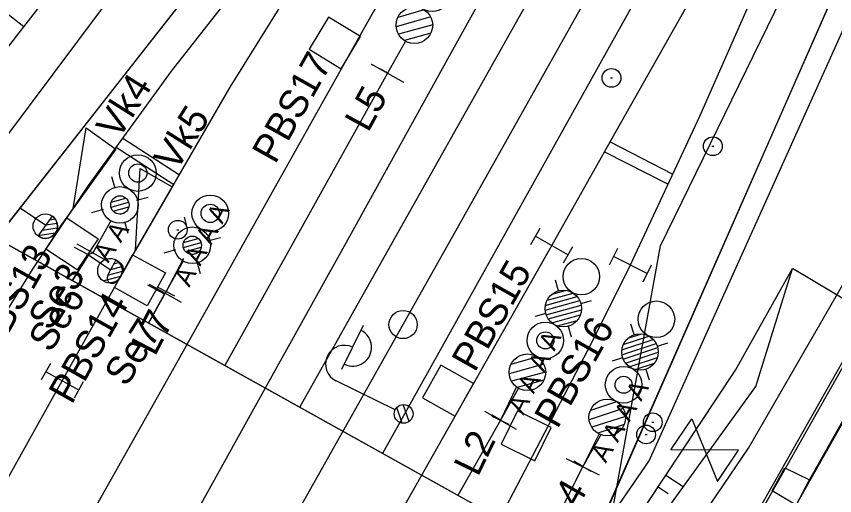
# Model space of a CAD drawing. Extents: x -781083 to -763634, y -1029516 to -1022695.
# Drawn here: x -765004.08 to -764960.51, y -1023880.88 to -1023855.35 of the extents above; entities that cross this region are included whole.
import ezdxf

# ---------------------------------------------------------------- set-up
doc = ezdxf.new("R2010")
doc.units = 0
for name, color, linetype in [('Default', 7, 'Continuous'), ('Hranice parcel', 7, 'Continuous'), ('PS120111-MOK', 7, 'Continuous'), ('PS_12-01-10_Kabelizace_nove_kabelizace', 7, 'Continuous'), ('PS_12-01-11_SZZ_Slany_nove_prvky', 7, 'Continuous'), ('PS_12-01-11_SZZ_Slany_nove_prvky_popis', 7, 'Continuous'), ('PS_12-01-11_SZZ_Slany_rusene_prvky', 7, 'Continuous'), ('PS_12-01-11_SZZ_Slany_rusene_prvky_popis', 7, 'Continuous'), ('SO128401_EOV_trasa', 7, 'Continuous'), ('Vnitřní kresba', 7, 'Continuous'), ('Vrstva 1', 7, 'Continuous'), ('Vrstva 17', 7, 'Continuous'), ('Vrstva 21', 7, 'Continuous'), ('Vrstva 23', 7, 'Continuous'), ('Vrstva 25', 7, 'Continuous'), ('Vrstva 3', 7, 'Continuous'), ('Vrstva 48', 7, 'Continuous'), ('Vrstva 49', 7, 'Continuous'), ('Vrstva 50', 7, 'Continuous'), ('Vrstva 7', 7, 'Continuous'), ('ČD Telematika_TK', 7, 'Continuous')]:
    doc.layers.add(name, color=color, linetype=linetype)

# ---------------------------------------------------------------- blocks, each defined once
blk = doc.blocks.new('C669')
at = {"layer": 'Vrstva 25'}
for p, q in [((0, 5), (0, 40)), ((7, 40), (33, 40)), ((-4.78, -1.46), (1.44, 4.76)), ((-2.39, -4.37), (4.38, 2.4))]:
    blk.add_line(p, q, dxfattribs=at)
blk.add_circle((0, 0), 5, dxfattribs=at)
for centre, start, end in [((10, 40), 0, 180), ((20, 39.88), 179.2974, 0.7026)]:
    blk.add_arc(centre, 10, start, end, dxfattribs=at)
blk = doc.blocks.new('C687')
at = {"layer": 'Vrstva 21'}
blk.add_lwpolyline([(-10, -15), (10, -15), (-10, 15), (10, 15), (-10, -15)], dxfattribs=at)
blk = doc.blocks.new('C053_4')
at = {"layer": 'Vrstva 50'}
blk.add_line((-0.5, 0), (0.5, 0), dxfattribs=at)
blk.add_circle((0, 0), 5, dxfattribs=at)
blk = doc.blocks.new('C649_1')
at = {"layer": 'Vrstva 3'}
for p, q in [((-5, 10), (5, 10)), ((0, 10), (0, -10)), ((-5, -10), (5, -10))]:
    blk.add_line(p, q, dxfattribs=at)
blk = doc.blocks.new('POINT_DISPLAY')
at = {"layer": 'Default'}
blk.add_line((0, 0), (0, 0), dxfattribs=at)
blk = doc.blocks.new('C335')
at = {"layer": 'Vrstva 7'}
blk.add_blockref('POINT_DISPLAY', (0, 0), dxfattribs=at)
blk = doc.blocks.new('C513_17')
at = {"layer": 'Vrstva 7'}
blk.add_circle((0, 0), 7.5, dxfattribs=at)
blk = doc.blocks.new('C016')
at = {"layer": 'PS_12-01-11_SZZ_Slany_rusene_prvky'}
for p, q in [((0.01, 5), (-0.01, -5)), ((19.8, 0), (0, 0))]:
    blk.add_line(p, q, dxfattribs=at)
blk = doc.blocks.new('C016_1')
at = {"layer": 'PS_12-01-11_SZZ_Slany_rusene_prvky'}
for p, q in [((0, 4.99), (0, -4.99)), ((19.8, 0), (0, 0))]:
    blk.add_line(p, q, dxfattribs=at)
blk = doc.blocks.new('NS12')
at = {"layer": 'PS_12-01-11_SZZ_Slany_nove_prvky'}
for p, q in [((-10.61, 115.61), (-17, 122)), ((10.61, 115.61), (17, 122)), ((-14.95, 104.3), (0.71, 119.96)), ((-14.06, 99.88), (5.12, 119.06)), ((-13.82, 110.73), (-5.7, 118.86)), ((-12.24, 96.4), (8.61, 117.25)), ((-9.72, 93.62), (11.4, 114.74)), ((-6.52, 91.51), (13.48, 111.52)), ((-2.5, 90.23), (14.77, 107.5)), ((2.88, 90.31), (14.72, 102.15)), ((-10.61, 94.39), (-17, 88)), ((10.61, 94.39), (17, 88)), ((0.97, 59.97), (-14.97, 44.03)), ((8.42, 57.42), (-12.42, 36.58)), ((12.99, 52.49), (-7.8, 32.19)), ((14.97, 45.97), (-1, 30)), ((0, 30), (0, 0)), ((-15, 0), (15, 0))]:
    blk.add_line(p, q, dxfattribs=at)
for centre, radius in [((0, 135), 15), ((0, 105), 15), ((0, 75), 15), ((0, 75), 7), ((0, 45), 15)]:
    blk.add_circle(centre, radius, dxfattribs=at)
blk = doc.blocks.new('NS12_1')
at = {"layer": 'PS_12-01-11_SZZ_Slany_nove_prvky'}
for p, q in [((-10.61, 115.61), (-17, 122)), ((10.61, 115.61), (17, 122)), ((-14.95, 104.3), (0.71, 119.96)), ((-14.06, 99.88), (5.12, 119.06)), ((-13.82, 110.73), (-5.7, 118.86)), ((-12.24, 96.4), (8.61, 117.25)), ((-9.72, 93.62), (11.4, 114.74)), ((-6.52, 91.51), (13.48, 111.52)), ((-2.5, 90.23), (14.77, 107.5)), ((2.88, 90.31), (14.72, 102.15)), ((-10.61, 94.39), (-17, 88)), ((10.61, 94.39), (17, 88)), ((0.97, 59.97), (-14.97, 44.03)), ((8.42, 57.42), (-12.42, 36.58)), ((12.99, 52.49), (-7.8, 32.19)), ((14.97, 45.97), (-1, 30)), ((0, 30), (0, 0)), ((-15, 0), (15, 0))]:
    blk.add_line(p, q, dxfattribs=at)
for centre, radius in [((0, 135), 15), ((0, 105), 15), ((0, 75), 15), ((0, 75), 7), ((0, 45), 15)]:
    blk.add_circle(centre, radius, dxfattribs=at)
blk = doc.blocks.new('NS12_2')
at = {"layer": 'PS_12-01-11_SZZ_Slany_nove_prvky'}
for p, q in [((-10.61, 115.61), (-17, 122)), ((10.61, 115.61), (17, 122)), ((-14.95, 104.3), (0.71, 119.96)), ((-14.06, 99.88), (5.12, 119.06)), ((-13.82, 110.73), (-5.7, 118.86)), ((-12.24, 96.4), (8.61, 117.25)), ((-9.72, 93.62), (11.4, 114.74)), ((-6.52, 91.51), (13.48, 111.52)), ((-2.5, 90.23), (14.77, 107.5)), ((2.88, 90.31), (14.72, 102.15)), ((-10.61, 94.39), (-17, 88)), ((10.61, 94.39), (17, 88)), ((0.97, 59.97), (-14.97, 44.03)), ((8.42, 57.42), (-12.42, 36.58)), ((12.99, 52.49), (-7.8, 32.19)), ((14.97, 45.97), (-1, 30)), ((0, 30), (0, 0)), ((-15, 0), (15, 0))]:
    blk.add_line(p, q, dxfattribs=at)
for centre, radius in [((0, 135), 15), ((0, 105), 15), ((0, 75), 15), ((0, 75), 7), ((0, 45), 15)]:
    blk.add_circle(centre, radius, dxfattribs=at)
blk = doc.blocks.new('C016_2')
at = {"layer": 'PS_12-01-11_SZZ_Slany_rusene_prvky'}
for p, q in [((0, 5), (0, -5)), ((19.81, 0), (0, 0))]:
    blk.add_line(p, q, dxfattribs=at)
blk = doc.blocks.new('NS5')
at = {"layer": 'PS_12-01-11_SZZ_Slany_nove_prvky'}
for p, q in [((-10, 55), (-17, 62)), ((10, 55), (17, 62)), ((-7.3, 43.39), (1.61, 52.3)), ((-5.47, 39.92), (5.1, 50.48)), ((-2.23, 37.85), (7.13, 47.21)), ((3.76, 38.54), (6.45, 41.23)), ((-10, 35), (-17, 28)), ((10, 35), (17, 28)), ((0, 30), (0, 0)), ((-15, 0), (15, 0))]:
    blk.add_line(p, q, dxfattribs=at)
for centre, radius in [((0, 75), 15), ((0, 75), 7.5), ((0, 45), 15), ((0, 45), 7.5)]:
    blk.add_circle(centre, radius, dxfattribs=at)
blk = doc.blocks.new('C649_1_1')
at = {"layer": 'PS_12-01-11_SZZ_Slany_rusene_prvky'}
for p, q in [((-5, 10), (5, 10)), ((0, 10), (0, -10)), ((-5, -10), (5, -10))]:
    blk.add_line(p, q, dxfattribs=at)
blk = doc.blocks.new('SB11_3')
at = {"layer": 'PS_12-01-11_SZZ_Slany_nove_prvky'}
blk.add_lwpolyline([(-119.5, 188.9), (-222.8, 18), (-51.7, -85.4), (51.7, 85.4)], close=True, dxfattribs=at)
blk = doc.blocks.new('SB11_4')
at = {"layer": 'PS_12-01-11_SZZ_Slany_nove_prvky'}
blk.add_lwpolyline([(-124.8, 185.5), (-223.3, 11.4), (-49.2, -87), (49.2, 87)], close=True, dxfattribs=at)
blk = doc.blocks.new('SB11_5')
at = {"layer": 'PS_12-01-11_SZZ_Slany_nove_prvky'}
blk.add_lwpolyline([(-135.8, 177), (-222.6, 0.5), (-43.4, -88.3), (43.4, 88.3)], close=True, dxfattribs=at)
blk = doc.blocks.new('VU26_1')
at = {"layer": 'PS_12-01-11_SZZ_Slany_nove_prvky'}
for p, q in [((-95, 20), (-75, 20)), ((-84.76, 10.01), (-94.75, 20)), ((-80.54, 11.09), (-89.45, 20)), ((-77.53, 13.38), (-84.15, 20)), ((-75.56, 16.72), (-78.84, 20)), ((-60, 10), (-85, 10))]:
    blk.add_line(p, q, dxfattribs=at)
blk.add_lwpolyline([(0, 10), (-60, 10), (0, 40)], close=True, dxfattribs=at)
blk.add_lwpolyline([(-95, 20), (-75, 20)], dxfattribs=at)
blk.add_circle((-85, 20), 10, dxfattribs=at)
blk.add_arc((-85, 20), 10, 179.99624, 0.00163, dxfattribs=at)
blk.add_arc((-85, 20), 10, 179.99624, 0.00163, dxfattribs=at)
blk = doc.blocks.new('SB11_13')
at = {"layer": 'PS_12-01-11_SZZ_Slany_nove_prvky'}
blk.add_lwpolyline([(221.9, -27.9), (110.8, -194.2), (-55.5, -83.2), (55.5, 83.2)], close=True, dxfattribs=at)
blk = doc.blocks.new('SB11_14')
at = {"layer": 'PS_12-01-11_SZZ_Slany_nove_prvky'}
blk.add_lwpolyline([(223.4, -9.5), (126.4, -184.4), (-48.5, -87.5), (48.5, 87.5)], close=True, dxfattribs=at)

msp = doc.modelspace()

# ---------------------------------------------------------------- linework, layer by layer
at = {"layer": 'Hranice parcel'}
msp.add_lwpolyline([(-764938.97, -1023836.45), (-764967.04, -1023886), (-764962.72, -1023888.96), (-764967.7, -1023897.5)], dxfattribs=at)
at = {"layer": 'PS120111-MOK'}
msp.add_lwpolyline([(-765225.805, -1024328.474), (-765227.041, -1024327.403), (-765189.607, -1024263.284), (-765167.089, -1024223.521), (-765111.836, -1024124.939), (-765108.851, -1024119.501), (-765085.73, -1024077.899), (-765081.023, -1024080.523), (-765060.822, -1024044.042), (-765057.835, -1024038.647), (-765021.888, -1023965.037), (-765009.529, -1023945.01), (-764990.029, -1023909.994), (-764973.93, -1023884.565), (-764957.796, -1023847.878), (-764953.349, -1023837.037), (-764952.504, -1023834.976), (-764951.393, -1023835.06)], dxfattribs=at)
at = {"layer": 'PS_12-01-10_Kabelizace_nove_kabelizace'}
for p, q in [((-765005.156, -1023867.179), (-764967.937, -1023819.655)), ((-764988.994, -1023876.176), (-764968.535, -1023839.77)), ((-764963.233, -1023840.29), (-764984.582, -1023878.634)), ((-764957.796, -1023847.878), (-764973.93, -1023884.565)), ((-764985.188, -1023857.891), (-764984.306, -1023858.363)), ((-764984.313, -1023858.377), (-764992.987, -1023873.955)), ((-765003.883, -1023865.554), (-765002.509, -1023866.483)), ((-764996.151, -1023870.095), (-764997.052, -1023871.691)), ((-764978.311, -1023876.86), (-764980.57, -1023880.867)), ((-764978.311, -1023876.86), (-764978.778, -1023876.58)), ((-764973.926, -1023879.33), (-764974.394, -1023879.05)), ((-764973.929, -1023879.336), (-764975.974, -1023883.426))]:
    msp.add_line(p, q, dxfattribs=at)
for points in [[(-764973.93, -1023884.565), (-765004.981, -1023867.276), (-765005.156, -1023867.179)], [(-765001.107, -1023869.434), (-765000.245, -1023868.058), (-765000.982, -1023867.665)], [(-765001.107, -1023869.434), (-765000.245, -1023868.058), (-764999.075, -1023868.849)], [(-765000.005, -1023867.946), (-765000.245, -1023868.058), (-765001.106, -1023869.433)], [(-764997.052, -1023871.691), (-764996.187, -1023870.158), (-764997.084, -1023869.662)]]:
    msp.add_lwpolyline(points, dxfattribs=at)
at = {"layer": 'PS_12-01-11_SZZ_Slany_nove_prvky'}
for p, q in [((-764997.73, -1023867.811), (-764998.539, -1023869.221)), ((-764998.612, -1023868.471), (-764998.903, -1023868.55)), ((-764998.456, -1023868.934), (-764999.246, -1023869.148)), ((-764998.488, -1023868.69), (-764999.075, -1023868.849)), ((-764998.532, -1023869.207), (-764999.418, -1023869.447))]:
    msp.add_line(p, q, dxfattribs=at)
msp.add_lwpolyline([(-764995.791, -1023864.428), (-764997.73, -1023867.811), (-764997.482, -1023863.458)], close=True, dxfattribs=at)
msp.add_ellipse((-764999.102, -1023868.897), major_axis=(0.546, -0.353), ratio=0.999982, dxfattribs=at)
msp.add_open_spline([(-764999.103, -1023868.897), (-764998.779, -1023868.333), (-764998.779, -1023868.333), (-764998.779, -1023868.333), (-764998.215, -1023868.657), (-764998.539, -1023869.22), (-764998.862, -1023869.784), (-764999.426, -1023869.461), (-764999.103, -1023868.897)], degree=4, dxfattribs=at)
at = {"layer": 'SO128401_EOV_trasa'}
for points in [[(-764973.93, -1023884.565), (-765005.156, -1023867.179), (-764967.937, -1023819.655), (-764942.036, -1023784.592), (-764937.448, -1023776.793), (-764936.433, -1023777.403)], [(-765060.824, -1024044.045), (-765057.835, -1024038.647), (-765021.888, -1023965.037), (-765009.529, -1023945.01), (-764990.029, -1023909.994), (-764973.93, -1023884.565), (-764973.93, -1023884.565), (-764957.796, -1023847.878), (-764957.796, -1023847.878), (-764953.349, -1023837.037), (-764953.349, -1023837.037), (-764952.595, -1023837.444), (-764952.595, -1023837.444), (-764952.595, -1023837.444), (-764952.595, -1023837.444)]]:
    msp.add_lwpolyline(points, dxfattribs=at)
at = {"layer": 'Vnitřní kresba'}
msp.add_line((-764947.74, -1023855.04), (-764963.43, -1023882.91), dxfattribs=at)
at = {"layer": 'Vrstva 1'}
for points in [[(-765011.125, -1023882.032), (-765006.787, -1023874.584), (-765003.188, -1023868.775), (-765000.244, -1023864.367), (-764995.829, -1023858.264), (-764991.795, -1023853.119), (-764989.992, -1023850.92), (-764988.125, -1023848.704), (-764979.186, -1023837.995), (-764972.943, -1023830.075), (-764972.169, -1023829.066), (-764962.145, -1023815.837), (-764953.22, -1023803.742), (-764952.283, -1023802.457), (-764942.467, -1023789.001), (-764933.609, -1023776.857), (-764932.714, -1023775.624), (-764932.358, -1023775.126), (-764928.839, -1023770.209), (-764926.844, -1023767.42), (-764917.098, -1023753.973), (-764910.61, -1023742.572)], [(-765057.199, -1024002.967), (-765051.483, -1023992.806), (-765043.706, -1023978.953), (-765034.751, -1023962.958), (-765025.899, -1023947.163), (-765016.568, -1023930.575), (-765007.818, -1023915.05), (-764998.815, -1023899.045), (-764993.349, -1023889.308), (-764987.511, -1023878.918), (-764981.006, -1023867.343), (-764973.154, -1023853.353), (-764966.496, -1023841.495), (-764959.274, -1023828.66), (-764951.948, -1023815.612), (-764946.772, -1023806.407), (-764938.618, -1023791.934), (-764931.244, -1023778.835), (-764930.485, -1023777.473), (-764927.033, -1023771.438), (-764925.317, -1023768.417), (-764917.098, -1023753.973)], [(-765061.157, -1024000.548), (-765054.406, -1023988.525), (-765046.25, -1023974.042), (-765038.306, -1023959.907), (-765029.522, -1023944.29), (-765019.951, -1023927.223), (-765010.85, -1023911.039), (-765002.788, -1023896.651), (-764999.751, -1023891.219), (-764995.793, -1023884.104), (-764991.163, -1023875.777), (-764986.062, -1023866.575), (-764981.011, -1023857.454), (-764976.168, -1023848.713), (-764971.336, -1023840.024), (-764966.193, -1023830.79), (-764963.989, -1023826.843), (-764958.821, -1023817.674), (-764953.901, -1023808.973), (-764950.727, -1023803.418), (-764942.467, -1023789.001)], [(-765021.966, -1023959.899), (-765020.98, -1023958.139), (-765020.338, -1023956.998), (-765016.5, -1023950.137), (-765007.832, -1023934.643), (-765003.16, -1023926.347), (-764995.027, -1023911.884), (-764988.083, -1023899.535), (-764983.024, -1023890.503), (-764978.046, -1023881.533), (-764973.443, -1023872.721), (-764971.379, -1023868.593), (-764967.7, -1023860.663), (-764964.253, -1023852.828), (-764961.628, -1023846.609), (-764955.193, -1023831.268), (-764949.378, -1023817.406), (-764948.769, -1023815.942), (-764946.974, -1023811.649), (-764945.113, -1023807.171), (-764938.618, -1023791.934)], [(-765066.823, -1024000.8), (-765059.521, -1023987.798), (-765051.083, -1023972.749), (-765042.307, -1023957.114), (-765034.527, -1023943.229), (-765024.842, -1023926.012), (-765014.604, -1023907.749), (-765007.197, -1023894.564), (-765001.299, -1023884.061), (-764995.865, -1023874.378), (-764990.286, -1023864.419), (-764985.503, -1023855.894), (-764983.132, -1023851.684), (-764978.128, -1023842.798), (-764973.494, -1023834.781), (-764970.63, -1023830.052), (-764962.145, -1023815.837)], [(-764992.669, -1023917.221), (-764979.299, -1023898.88), (-764973.72, -1023891.071), (-764965.108, -1023878.355), (-764944.509, -1023842.632), (-764937.461, -1023829.77)], [(-765052.709, -1024004.781), (-765046.025, -1023992.89), (-765034.924, -1023973.118), (-765026.269, -1023957.734), (-765017.76, -1023942.588), (-765010.012, -1023928.764), (-765001.938, -1023914.334), (-764994.407, -1023900.905), (-764986.605, -1023887.067), (-764981.397, -1023877.846), (-764975.574, -1023867.554), (-764972.605, -1023862.288), (-764968.241, -1023854.565), (-764963.27, -1023845.769), (-764955.193, -1023831.268)], [(-765076.991, -1024009.249), (-765068.63, -1023994.356), (-765060.962, -1023980.666), (-765051.422, -1023963.636), (-765043.392, -1023949.298), (-765036.095, -1023936.274), (-765028.081, -1023921.999), (-765021.192, -1023909.705), (-765014.101, -1023897.058), (-765011.259, -1023891.988), (-765007.442, -1023885.157), (-765001.636, -1023874.768), (-764998.254, -1023868.714), (-764992.689, -1023859.115), (-764988.392, -1023852.179), (-764986.762, -1023849.668), (-764979.186, -1023837.995)]]:
    msp.add_lwpolyline(points, dxfattribs=at)
at = {"layer": 'Vrstva 17'}
for points in [[(-764984.37, -1023833.783), (-764994.207, -1023847.799), (-765035.2, -1023902.657), (-765053.308, -1023935.706), (-765077.185, -1023979.953), (-765108.689, -1023993.473), (-765147.863, -1024026.342)], [(-764965.992, -1023885.405), (-764965.453, -1023883.54), (-764958.526, -1023871.297), (-764951.567, -1023858.868)], [(-764958.526, -1023871.297), (-764962.765, -1023868.78)]]:
    msp.add_lwpolyline(points, dxfattribs=at)
at = {"layer": 'Vrstva 23'}
for points in [[(-764962.559, -1023881.396), (-764961.849, -1023880.039), (-764932.414, -1023827.868)], [(-764962.559, -1023881.396), (-764963.834, -1023880.627), (-764963.157, -1023879.401), (-764961.849, -1023880.039), (-764962.559, -1023881.396)]]:
    msp.add_lwpolyline(points, dxfattribs=at)
at = {"layer": 'Vrstva 48'}
for p, q in [((-765007.467, -1023852.954), (-765003.682, -1023855.896)), ((-764968.582, -1023880.415), (-764969.505, -1023879.805)), ((-764969.38, -1023880.786), (-764969.918, -1023880.43))]:
    msp.add_line(p, q, dxfattribs=at)
at = {"layer": 'Vrstva 49'}
for points in [[(-765026.593, -1023885.365), (-764999.705, -1023850.781), (-764986.63, -1023833.272), (-764978.594, -1023818.199), (-764974.02, -1023810.068), (-764969.31, -1023798.584)], [(-764984.64, -1023902.67), (-764964.718, -1023875.061), (-764962.765, -1023868.78)], [(-764984.64, -1023902.67), (-764965.796, -1023874.202), (-764962.765, -1023868.78)]]:
    msp.add_lwpolyline(points, dxfattribs=at)
at = {"layer": 'Vrstva 7'}
for p, q in [((-764998.41, -1023861.832), (-764995.398, -1023863.788)), ((-764972.466, -1023862.042), (-764969.134, -1023863.753)), ((-764998.762, -1023862.319), (-764995.699, -1023864.307)), ((-764972.762, -1023862.565), (-764969.386, -1023864.298))]:
    msp.add_line(p, q, dxfattribs=at)
at = {"layer": 'ČD Telematika_TK'}
for points in [[(-764972.556, -1023882.882), (-764969.78, -1023867.575), (-764954.962, -1023837.207), (-764946.646, -1023819.145), (-764922.208, -1023770.145), (-764907.866, -1023743.998)], [(-765046.807, -1024017.08), (-765029.13, -1023984.48), (-765018.689, -1023963.431), (-765009.158, -1023943.676), (-764986.584, -1023911.367), (-764975.521, -1023895.82), (-764979.204, -1023891.861), (-764970.396, -1023879.031), (-764960.103, -1023856.143), (-764944.124, -1023819.068), (-764943.31, -1023819.61)]]:
    msp.add_lwpolyline(points, dxfattribs=at)

# ---------------------------------------------------------------- block references
at = {"layer": 'PS_12-01-11_SZZ_Slany_nove_prvky'}
for name, p, xscale, yscale, rotation in [('NS12_2', (-764984.313, -1023858.377), 0.065, 0.065, -29.116206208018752), ('VU26_1', (-764998.25, -1023862.813), 0.06500000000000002, 0.065, 54.11746937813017), ('NS5', (-765000.005, -1023867.946), 0.065, 0.06499999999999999, -29.387467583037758), ('NS5', (-764996.152, -1023870.095), 0.065, 0.06499999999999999, -29.387467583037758), ('NS12_1', (-764978.311, -1023876.86), 0.06499999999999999, 0.06499999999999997, -29.414544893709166), ('NS12', (-764973.929, -1023879.336), 0.065, 0.065, -26.565051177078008)]:
    msp.add_blockref(name, p, dxfattribs=dict(at, xscale=xscale, yscale=yscale, rotation=rotation))
for name, p, xscale, yscale in [('SB11_3', (-764986.267, -1023857.286), 0.010000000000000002, 0.010000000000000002), ('SB11_13', (-765001.949, -1023866.92), 0.010000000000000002, 0.010000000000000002), ('SB11_14', (-764998.374, -1023868.922), 0.010000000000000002, 0.010000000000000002), ('SB11_4', (-764980.228, -1023875.779), 0.01, 0.01), ('SB11_5', (-764976.035, -1023878.142), 0.010000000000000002, 0.010000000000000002)]:
    msp.add_blockref(name, p, dxfattribs=dict(at, xscale=xscale, yscale=yscale))
at = {"layer": 'PS_12-01-11_SZZ_Slany_rusene_prvky'}
for name, p, xscale, yscale, rotation in [('C649_1_1', (-764975.574, -1023867.554), 0.10000000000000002, 0.1, 60.499719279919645), ('C649_1_1', (-764971.379, -1023868.593), 0.1, 0.10000000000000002, 63.43494882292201), ('C016_2', (-764996.108, -1023870.003), 0.10000000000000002, 0.10000000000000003, 62.37581335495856), ('C016', (-764978.311, -1023876.86), 0.1, 0.10000000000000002, 64.06234081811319), ('C016_1', (-764973.929, -1023879.336), 0.09999999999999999, 0.09999999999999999, 60.35324000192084)]:
    msp.add_blockref(name, p, dxfattribs=dict(at, xscale=xscale, yscale=yscale, rotation=rotation))
at = {"layer": 'Vrstva 21', "xscale": 0.10000000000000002, "yscale": 0.10000000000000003, "rotation": 55.89191157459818}
msp.add_blockref('C687', (-764967.437, -1023878.452), dxfattribs=at)
at = {"layer": 'Vrstva 25', "xscale": 0.09999999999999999, "yscale": 0.09999999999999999, "rotation": 63.945152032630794}
msp.add_blockref('C669', (-764983.461, -1023876.53), dxfattribs=at)
at = {"layer": 'Vrstva 3'}
for p, xscale, yscale, rotation in [((-764975.574, -1023867.554), 0.10000000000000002, 0.1, 60.499719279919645), ((-764971.379, -1023868.593), 0.1, 0.10000000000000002, 63.43494882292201), ((-765001.636, -1023874.768), 0.09999999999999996, 0.09999999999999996, -119.18942500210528)]:
    msp.add_blockref('C649_1', p, dxfattribs=dict(at, xscale=xscale, yscale=yscale, rotation=rotation))
at = {"layer": 'Vrstva 50', "xscale": 0.1, "yscale": 0.10000000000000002}
for p in [(-764972.396, -1023858.63), (-764966.998, -1023862.269), (-764995.488, -1023866.717), (-764970.199, -1023876.974), (-764970.552, -1023877.624)]:
    msp.add_blockref('C053_4', p, dxfattribs=at)
at = {"layer": 'Vrstva 7'}
for name, p, xscale, yscale, rotation in [('C335', (-764997.116, -1023863.03), 0.10000000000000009, 0.10000000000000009, 90), ('C335', (-764970.944, -1023863.161), 0.10000000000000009, 0.10000000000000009, 90), ('C513_17', (-764983.493, -1023871.769), 0.10000000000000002, 0.1, -119.33542242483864)]:
    msp.add_blockref(name, p, dxfattribs=dict(at, xscale=xscale, yscale=yscale, rotation=rotation))

# ---------------------------------------------------------------- texts
at = {"layer": 'PS_12-01-11_SZZ_Slany_nove_prvky_popis'}
for s, rotation, p in [('PBS17', 60.6062, (-764990.299, -1023863.272)), ('Vk4', 57.7603, (-764998.646, -1023861.976)), ('L5', 61.4283, (-764985.35, -1023861.584)), ('Vk5', 57.7603, (-764995.576, -1023863.673)), ('PBS13', 60.6062, (-765005.186, -1023873.504)), ('PBS15', 60.6062, (-764979.673, -1023874.359)), ('Se6', 57.7603, (-765002.26, -1023873.325)), ('PBS14', 60.6062, (-765001.128, -1023876.077)), ('Se7', 57.7603, (-764998.22, -1023875.142)), ('PBS16', 60.6062, (-764975.273, -1023877.374)), ('L2', 64.0623, (-764979.504, -1023879.918)), ('L4', 60.3532, (-764974.749, -1023882.543))]:
    msp.add_text(s, height=1.5, rotation=rotation, dxfattribs=at).set_placement(p)
at = {"layer": 'PS_12-01-11_SZZ_Slany_rusene_prvky'}
for s, rotation, p in [('  A A A A ', 62.3758, (-764995.222, -1023870.467)), ('A A ', 57.7603, (-764999.193, -1023868.519)), ('  A A A A ', 64.0623, (-764977.412, -1023877.297)), ('  A A A A ', 60.3532, (-764973.06, -1023879.831))]:
    msp.add_text(s, height=1, rotation=rotation, dxfattribs=at).set_placement(p)
at = {"layer": 'PS_12-01-11_SZZ_Slany_rusene_prvky_popis'}
for s, rotation, p in [('Se3', 57.7603, (-765002.275, -1023872.163)), ('L7', 62.3758, (-764996.704, -1023873.509))]:
    msp.add_text(s, height=1.5, rotation=rotation, dxfattribs=at).set_placement(p)

doc.saveas('drawing.dxf')
